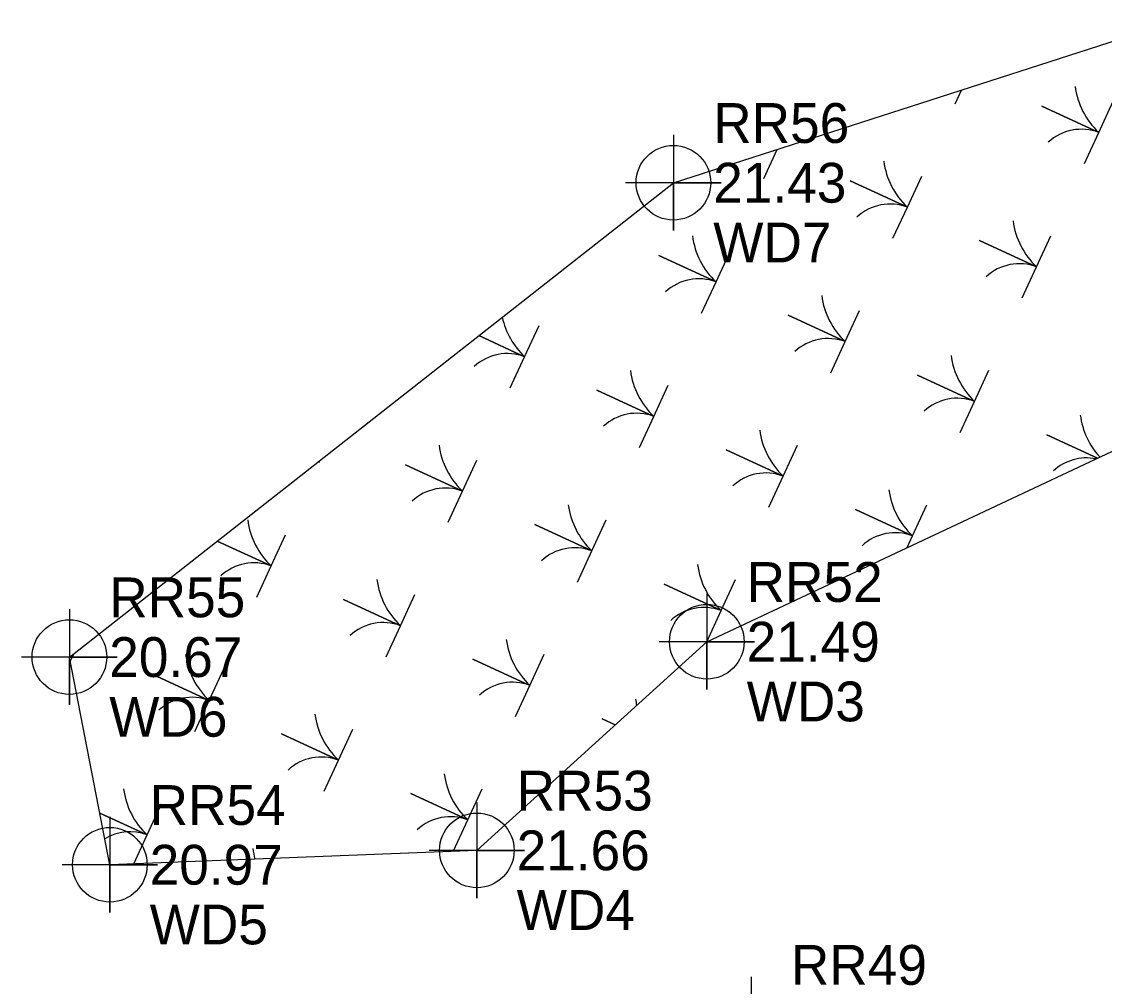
# Model space of a CAD drawing. Extents: x 2532037 to 2533565, y 713396 to 716867.
# Drawn here: x 2532864 to 2532932, y 715885.8 to 715946.4 of the extents above; entities that cross this region are included whole.
import ezdxf

# ---------------------------------------------------------------- set-up
doc = ezdxf.new("R2010")
doc.units = 0
for name, color, linetype in [('Exist Environmental Wetland Boundary', 7, 'Continuous'), ('Exist Environmental Wetland Boundary Cogo Comment', 7, 'Continuous'), ('Exist Environmental Wetland Boundary Cogo Elevation', 7, 'Continuous'), ('Exist Environmental Wetland Boundary Cogo Number', 7, 'Continuous'), ('Exist Environmental Wetland Boundary Cogo Point CELL', 7, 'Continuous'), ('Exist Horizontal Alignment', 7, 'Continuous'), ('Exist Right of Way Line', 7, 'Continuous'), ('Scratch_Level_1', 7, 'Continuous')]:
    doc.layers.add(name, color=color, linetype=linetype)

msp = doc.modelspace()

# ---------------------------------------------------------------- linework, layer by layer
at = {"layer": 'Exist Environmental Wetland Boundary'}
for p, q in [((2532904.959, 715936.28), (2532936.4, 715946.395)), ((2532867.016, 715906.496), (2532904.959, 715936.28)), ((2532907.057, 715907.461), (2532948.197, 715926.799)), ((2532907.057, 715907.461), (2532892.611, 715894.361)), ((2532869.557, 715893.457), (2532867.016, 715906.496)), ((2532892.611, 715894.361), (2532869.557, 715893.457))]:
    msp.add_line(p, q, dxfattribs=at)
at = {"layer": 'Exist Environmental Wetland Boundary Cogo Point CELL'}
for points in [[(2532904.959, 715939.28), (2532904.959, 715933.28), (2532904.959, 715936.28), (2532907.959, 715936.28), (2532901.959, 715936.28)], [(2532907.057, 715910.461), (2532907.057, 715904.461), (2532907.057, 715907.461), (2532910.057, 715907.461), (2532904.057, 715907.461)], [(2532867.016, 715909.496), (2532867.016, 715903.496), (2532867.016, 715906.496), (2532870.016, 715906.496), (2532864.016, 715906.496)], [(2532892.611, 715897.361), (2532892.611, 715891.361), (2532892.611, 715894.361), (2532895.611, 715894.361), (2532889.611, 715894.361)], [(2532869.557, 715896.457), (2532869.557, 715890.457), (2532869.557, 715893.457), (2532872.557, 715893.457), (2532866.557, 715893.457)], [(2532909.836, 715886.418), (2532909.836, 715880.418), (2532909.836, 715883.418), (2532912.836, 715883.418), (2532906.836, 715883.418)]]:
    msp.add_lwpolyline(points, dxfattribs=at)
for centre in [(2532904.959, 715936.28), (2532907.057, 715907.461), (2532867.016, 715906.496), (2532892.611, 715894.361), (2532869.557, 715893.457)]:
    msp.add_circle(centre, 2.344, dxfattribs=at)
at = {"layer": 'Exist Horizontal Alignment'}
msp.add_arc((2534464.186, 715033.977), 1700, 148.477837, 155.05, dxfattribs=at)
at = {"layer": 'Exist Right of Way Line'}
msp.add_arc((2534464.186, 715033.977), 1730, 148.477837, 155.05, dxfattribs=at)
at = {"layer": 'Scratch_Level_1'}
for p, q in [((2532922.651, 715941.238), (2532923.048, 715942.1)), ((2532910.631, 715936.543), (2532911.477, 715938.377)), ((2532882.693, 715918.709), (2532882.76, 715918.854)), ((2532867.071, 715906.213), (2532867.308, 715906.725))]:
    msp.add_line(p, q, dxfattribs=at)
for points in [[(2532930.772, 715937.489), (2532931.674, 715939.441), (2532928.092, 715941.095), (2532931.674, 715939.441), (2532932.575, 715941.394)], [(2532918.752, 715932.794), (2532919.654, 715934.746), (2532916.072, 715936.4), (2532919.654, 715934.746), (2532920.555, 715936.699)], [(2532926.874, 715929.045), (2532927.775, 715930.997), (2532924.193, 715932.651), (2532927.775, 715930.997), (2532928.676, 715932.949)], [(2532906.732, 715928.099), (2532907.634, 715930.051), (2532904.052, 715931.705), (2532907.634, 715930.051), (2532908.535, 715932.004)], [(2532914.854, 715924.35), (2532915.755, 715926.302), (2532912.173, 715927.956), (2532915.755, 715926.302), (2532916.657, 715928.255)], [(2532892.736, 715926.685), (2532895.614, 715925.356), (2532896.515, 715927.309)], [(2532894.713, 715923.404), (2532895.614, 715925.356), (2532892.736, 715926.685)], [(2532922.975, 715920.6), (2532923.877, 715922.553), (2532920.295, 715924.206), (2532923.877, 715922.553), (2532924.778, 715924.505)], [(2532902.834, 715919.655), (2532903.735, 715921.607), (2532900.153, 715923.261), (2532903.735, 715921.607), (2532904.637, 715923.56)], [(2532931.589, 715918.992), (2532928.416, 715920.457), (2532931.589, 715918.992)], [(2532910.955, 715915.905), (2532911.857, 715917.858), (2532908.275, 715919.511), (2532911.857, 715917.858), (2532912.758, 715919.81)], [(2532890.814, 715914.96), (2532891.715, 715916.912), (2532888.134, 715918.566), (2532891.715, 715916.912), (2532892.617, 715918.865)], [(2532919.64, 715913.376), (2532919.978, 715914.108), (2532916.396, 715915.762), (2532919.978, 715914.108), (2532920.88, 715916.061)], [(2532898.936, 715911.21), (2532899.837, 715913.163), (2532896.255, 715914.816), (2532899.837, 715913.163), (2532900.738, 715915.115)], [(2532876.301, 715913.784), (2532879.696, 715912.217), (2532880.597, 715914.17)], [(2532878.794, 715910.265), (2532879.696, 715912.217), (2532876.301, 715913.784)], [(2532907.057, 715907.461), (2532907.958, 715909.413), (2532904.376, 715911.067), (2532907.958, 715909.413), (2532908.86, 715911.366)], [(2532886.916, 715906.515), (2532887.817, 715908.468), (2532884.235, 715910.121), (2532887.817, 715908.468), (2532888.718, 715910.42)], [(2532895.037, 715902.766), (2532895.938, 715904.718), (2532892.357, 715906.372), (2532895.938, 715904.718), (2532896.84, 715906.671)], [(2532874.896, 715901.82), (2532875.797, 715903.773), (2532872.215, 715905.426), (2532875.797, 715903.773), (2532876.698, 715905.725)], [(2532901.302, 715902.242), (2532900.478, 715902.623), (2532901.302, 715902.242)], [(2532883.017, 715898.071), (2532883.919, 715900.023), (2532880.337, 715901.677), (2532883.919, 715900.023), (2532884.82, 715901.976)], [(2532891.139, 715894.322), (2532892.04, 715896.274), (2532888.458, 715897.928), (2532892.04, 715896.274), (2532892.941, 715898.226)], [(2532868.925, 715896.701), (2532871.899, 715895.328), (2532872.8, 715897.281)], [(2532871.062, 715893.516), (2532871.899, 715895.328), (2532868.925, 715896.701)]]:
    msp.add_lwpolyline(points, dxfattribs=at)
for centre, radius, start, end in [((2532934.961, 715942.947), 4.806, 187.34643, 226.84116), ((2532930.59, 715936.564), 3.075, 69.35932, 132.75394), ((2532922.941, 715938.252), 4.806, 187.34643, 226.84116), ((2532918.57, 715931.869), 3.075, 69.35932, 132.75394), ((2532931.062, 715934.503), 4.806, 187.34643, 226.84116), ((2532910.921, 715933.557), 4.806, 187.34643, 226.84116), ((2532926.691, 715928.12), 3.075, 69.35932, 132.75394), ((2532906.55, 715927.174), 3.075, 69.35932, 132.75394), ((2532919.042, 715929.808), 4.806, 187.34643, 226.84116), ((2532898.901, 715928.862), 4.806, 192.29189, 226.84116), ((2532914.671, 715923.425), 3.075, 69.35932, 132.75394), ((2532894.53, 715922.479), 3.075, 69.35932, 132.75394), ((2532927.164, 715926.058), 4.806, 187.34643, 226.84116), ((2532907.023, 715925.113), 4.806, 187.34643, 226.84116), ((2532922.793, 715919.676), 3.075, 69.35932, 132.75394), ((2532902.652, 715918.73), 3.075, 69.35932, 132.75394), ((2532935.285, 715922.309), 4.806, 187.34643, 222.47617), ((2532915.144, 715921.363), 4.806, 187.34643, 226.84116), ((2532895.003, 715920.418), 4.806, 187.34643, 226.84116), ((2532930.914, 715915.926), 3.075, 79.1926, 132.75394), ((2532910.773, 715914.981), 3.075, 69.35932, 132.75394), ((2532890.632, 715914.035), 3.075, 69.35932, 132.75394), ((2532923.265, 715917.614), 4.806, 187.34643, 226.84116), ((2532903.124, 715916.668), 4.806, 187.34643, 226.84116), ((2532882.983, 715915.723), 4.806, 187.34643, 226.84116), ((2532918.894, 715911.231), 3.075, 69.35932, 132.75394), ((2532898.753, 715910.286), 3.075, 69.35932, 132.75394), ((2532878.612, 715909.34), 3.075, 69.35932, 132.75394), ((2532911.246, 715912.919), 4.806, 187.34643, 226.84116), ((2532891.104, 715911.973), 4.806, 187.34643, 226.84116), ((2532906.875, 715906.536), 3.075, 69.35932, 132.75394), ((2532886.733, 715905.591), 3.075, 69.35932, 132.75394), ((2532899.226, 715908.224), 4.806, 187.34643, 226.84116), ((2532879.084, 715907.278), 4.806, 187.34643, 226.84116), ((2532894.855, 715901.841), 3.075, 69.35932, 132.75394), ((2532874.713, 715900.896), 3.075, 69.35932, 132.75394), ((2532907.347, 715904.475), 4.806, 187.34643, 192.14322), ((2532887.206, 715903.529), 4.806, 187.34643, 226.84116), ((2532882.835, 715897.146), 3.075, 69.35932, 132.75394), ((2532895.327, 715899.78), 4.806, 187.34643, 226.84116), ((2532875.186, 715898.834), 4.806, 187.34643, 226.84116), ((2532890.956, 715893.397), 3.075, 69.35932, 132.75394), ((2532870.815, 715892.451), 3.075, 69.35932, 120.84239), ((2532883.307, 715895.085), 4.806, 187.34643, 195.32539)]:
    msp.add_arc(centre, radius, start, end, dxfattribs=at)

# ---------------------------------------------------------------- texts
at = {"layer": 'Exist Environmental Wetland Boundary Cogo Comment'}
for s, p in [('WD7', (2532907.459, 715931.28)), ('WD3', (2532909.557, 715902.461)), ('WD6', (2532869.516, 715901.496)), ('WD4', (2532895.111, 715889.361)), ('WD5', (2532872.057, 715888.457))]:
    msp.add_text(s, height=2.5, dxfattribs=at).set_placement(p)
at = {"layer": 'Exist Environmental Wetland Boundary Cogo Elevation'}
for s, p in [('21.43', (2532907.459, 715935.03)), ('21.49', (2532909.557, 715906.211)), ('20.67', (2532869.516, 715905.246)), ('21.66', (2532895.111, 715893.111)), ('20.97', (2532872.057, 715892.207))]:
    msp.add_text(s, height=2.5, dxfattribs=at).set_placement(p)
at = {"layer": 'Exist Environmental Wetland Boundary Cogo Number'}
for s, p in [('RR56', (2532907.459, 715938.78)), ('RR52', (2532909.557, 715909.961)), ('RR55', (2532869.516, 715908.996)), ('RR53', (2532895.111, 715896.861)), ('RR54', (2532872.057, 715895.957)), ('RR49', (2532912.336, 715885.918))]:
    msp.add_text(s, height=2.5, dxfattribs=at).set_placement(p)

doc.saveas('drawing.dxf')
